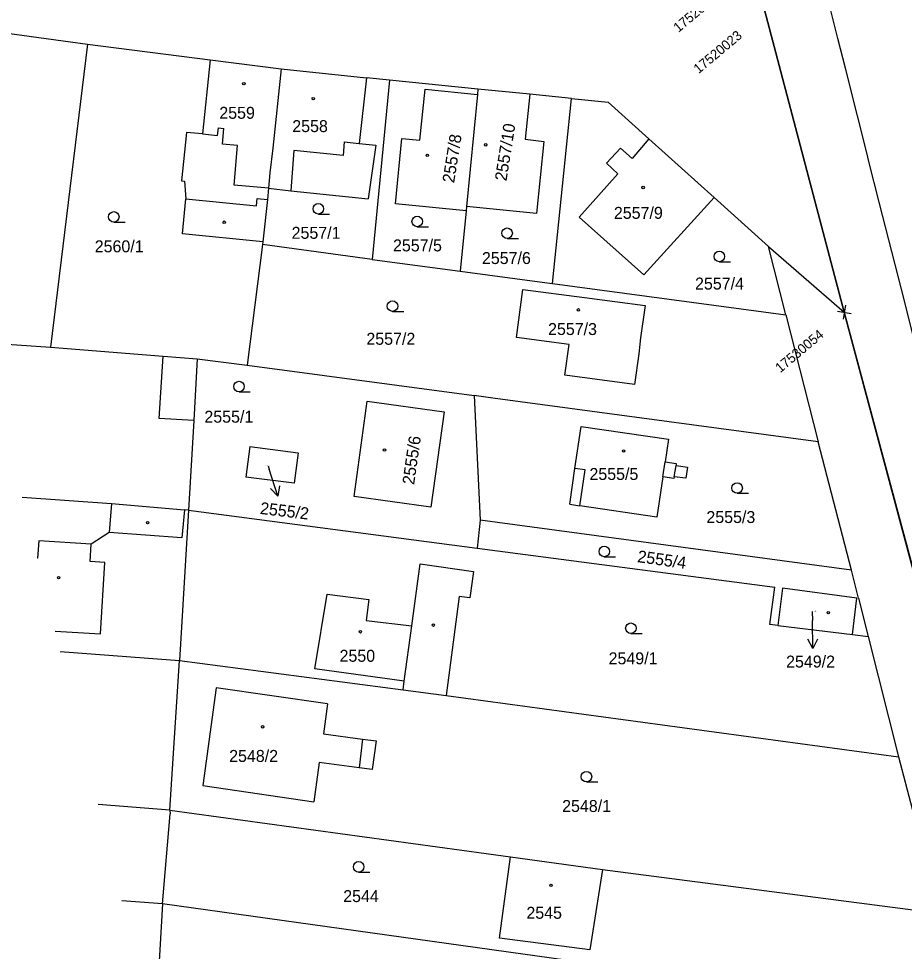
# Model space of a CAD drawing. Extents: x -754679 to -754173, y -1169241 to -1168288.
# Drawn here: x -754474.1 to -754379.7, y -1169048.7 to -1168949.2 of the extents above; entities that cross this region are included whole.
import ezdxf

# ---------------------------------------------------------------- set-up
doc = ezdxf.new("R2010")
doc.units = 0
for name, color, linetype in [('Vrstva 1', 7, 'Continuous'), ('Vrstva 16', 7, 'Continuous'), ('Vrstva 18', 7, 'Continuous'), ('Vrstva 19', 7, 'Continuous'), ('Vrstva 25', 7, 'Continuous'), ('Vrstva 4', 7, 'Continuous'), ('Vrstva 52', 7, 'Continuous'), ('Vrstva 53', 7, 'Continuous'), ('Vrstva 60', 7, 'Continuous')]:
    doc.layers.add(name, color=color, linetype=linetype)

msp = doc.modelspace()

# ---------------------------------------------------------------- linework, layer by layer
at = {"layer": 'Vrstva 1'}
for p, q in [((-754394.57, -1168948.26), (-754386.06, -1168980.52)), ((-754481.59, -1168949.91), (-754466.73, -1168951.94)), ((-754466.73, -1168951.94), (-754470.7, -1168984.24)), ((-754466.73, -1168951.94), (-754453.68, -1168953.61)), ((-754453.68, -1168953.61), (-754454.48, -1168961.5)), ((-754453.68, -1168953.61), (-754446.09, -1168954.58)), ((-754446.09, -1168954.58), (-754446.98, -1168963.03)), ((-754446.09, -1168954.58), (-754437, -1168955.53)), ((-754437, -1168955.53), (-754437.78, -1168962.52)), ((-754434.53, -1168955.78), (-754437, -1168955.53)), ((-754434.53, -1168955.78), (-754436.38, -1168974.88)), ((-754425.12, -1168956.72), (-754434.53, -1168955.78)), ((-754431.33, -1168962.16), (-754430.76, -1168956.72)), ((-754430.76, -1168956.72), (-754425.18, -1168957.29)), ((-754425.18, -1168957.29), (-754426.34, -1168969.24)), ((-754425.12, -1168956.72), (-754425.18, -1168957.29)), ((-754419.59, -1168957.27), (-754425.12, -1168956.72)), ((-754419.59, -1168957.27), (-754420.07, -1168962.07)), ((-754415.14, -1168957.72), (-754419.59, -1168957.27)), ((-754417.17, -1168977.46), (-754415.14, -1168957.72)), ((-754415.14, -1168957.72), (-754411.25, -1168958.11)), ((-754411.25, -1168958.11), (-754406.9, -1168962.02)), ((-754456.19, -1168961.34), (-754456.71, -1168966.5)), ((-754454.48, -1168961.5), (-754456.19, -1168961.34)), ((-754433.91, -1168968.96), (-754433.24, -1168962)), ((-754433.24, -1168962), (-754431.33, -1168962.16)), ((-754420.07, -1168962.07), (-754418.08, -1168962.31)), ((-754418.08, -1168962.31), (-754418.86, -1168969.98)), ((-754406.9, -1168962.02), (-754408.69, -1168964.11)), ((-754406.9, -1168962.02), (-754399.92, -1168968.29)), ((-754446.98, -1168963.03), (-754447.3, -1168965.65)), ((-754437.78, -1168962.52), (-754436.02, -1168962.72)), ((-754436.02, -1168962.72), (-754436.82, -1168968.44)), ((-754409.93, -1168963.02), (-754411.4, -1168964.64)), ((-754408.69, -1168964.11), (-754409.93, -1168963.02)), ((-754411.4, -1168964.64), (-754410.19, -1168965.77)), ((-754447.3, -1168965.65), (-754447.44, -1168967.3)), ((-754410.19, -1168965.77), (-754414.34, -1168970.38)), ((-754456.71, -1168966.5), (-754456.41, -1168966.53)), ((-754456.41, -1168966.53), (-754456.27, -1168968.44)), ((-754447.44, -1168967.3), (-754447.56, -1168968.51)), ((-754447.44, -1168967.3), (-754445.06, -1168967.58)), ((-754456.63, -1168972.16), (-754456.27, -1168968.44)), ((-754445.06, -1168967.58), (-754436.82, -1168968.44)), ((-754407.44, -1168976.53), (-754399.92, -1168968.29)), ((-754399.92, -1168968.29), (-754394.13, -1168973.5)), ((-754447.56, -1168968.51), (-754448.05, -1168973.02)), ((-754426.39, -1168969.71), (-754433.91, -1168968.96)), ((-754426.34, -1168969.24), (-754426.39, -1168969.71)), ((-754418.86, -1168969.98), (-754426.34, -1168969.24)), ((-754426.39, -1168969.71), (-754427.02, -1168976.13)), ((-754414.34, -1168970.38), (-754407.44, -1168976.53)), ((-754448.05, -1168973.02), (-754456.63, -1168972.16)), ((-754448.09, -1168973.3), (-754449.71, -1168986.17)), ((-754448.05, -1168973.02), (-754448.09, -1168973.3)), ((-754436.38, -1168974.88), (-754448.09, -1168973.3)), ((-754394.13, -1168973.5), (-754386.06, -1168980.52)), ((-754392.28, -1168980.8), (-754394.13, -1168973.5)), ((-754436.38, -1168974.88), (-754427.02, -1168976.13)), ((-754427.02, -1168976.13), (-754418.28, -1168977.31)), ((-754418.28, -1168977.31), (-754417.17, -1168977.46)), ((-754421.01, -1168983.23), (-754420.33, -1168978.08)), ((-754420.33, -1168978.08), (-754413.76, -1168978.94)), ((-754417.17, -1168977.46), (-754392.28, -1168980.8)), ((-754413.76, -1168978.94), (-754407.29, -1168979.79)), ((-754407.29, -1168979.79), (-754407.79, -1168983.26)), ((-754392.28, -1168980.8), (-754388.85, -1168994.33)), ((-754386.06, -1168980.52), (-754345.91, -1169130.8)), ((-754415.4, -1168983.97), (-754421.01, -1168983.23)), ((-754407.79, -1168983.26), (-754407.98, -1168984.94)), ((-754477.805, -1168983.743), (-754470.7, -1168984.24)), ((-754470.7, -1168984.24), (-754458.69, -1168985.2)), ((-754415.84, -1168987.24), (-754415.4, -1168983.97)), ((-754458.69, -1168985.2), (-754455.05, -1168985.5)), ((-754407.98, -1168984.94), (-754408.42, -1168988.22)), ((-754455.05, -1168985.5), (-754455.42, -1168992.07)), ((-754455.05, -1168985.5), (-754449.71, -1168986.17)), ((-754449.71, -1168986.17), (-754425.52, -1168989.41)), ((-754408.42, -1168988.22), (-754415.84, -1168987.24)), ((-754438.33, -1169000.18), (-754436.92, -1168989.99)), ((-754436.92, -1168989.99), (-754428.72, -1168991.13)), ((-754425.52, -1168989.41), (-754424.88, -1169002.68)), ((-754423.54, -1168989.68), (-754425.52, -1168989.41)), ((-754388.85, -1168994.33), (-754423.54, -1168989.68)), ((-754428.72, -1168991.13), (-754430.14, -1169001.31)), ((-754455.42, -1168992.07), (-754455.96, -1169001.63)), ((-754414.78, -1168997.18), (-754414.13, -1168992.71)), ((-754414.13, -1168992.71), (-754404.82, -1168994.06)), ((-754404.82, -1168994.06), (-754405.17, -1168996.48)), ((-754385.31, -1169008.03), (-754388.85, -1168994.33)), ((-754449.45, -1168994.84), (-754449.88, -1168998.11)), ((-754449.45, -1168994.84), (-754444.3, -1168995.53)), ((-754444.3, -1168995.53), (-754444.71, -1168998.76)), ((-754415.33, -1169000.99), (-754414.78, -1168997.18)), ((-754405.17, -1168996.48), (-754403.97, -1168996.66)), ((-754403.97, -1168996.66), (-754404, -1168996.86)), ((-754404, -1168996.86), (-754402.76, -1168997.04)), ((-754402.76, -1168997.04), (-754402.95, -1168998.23)), ((-754444.71, -1168998.76), (-754449.88, -1168998.11)), ((-754405.4, -1168998.07), (-754406.03, -1169002.37)), ((-754404.22, -1168998.25), (-754405.4, -1168998.07)), ((-754404.19, -1168998.06), (-754404.22, -1168998.25)), ((-754402.95, -1168998.23), (-754404.19, -1168998.06)), ((-754473.723, -1169000.249), (-754464.18, -1169000.91)), ((-754430.14, -1169001.31), (-754438.33, -1169000.18)), ((-754464.18, -1169000.91), (-754464.45, -1169004)), ((-754464.18, -1169000.91), (-754456.41, -1169001.59)), ((-754415.33, -1169000.99), (-754414.24, -1169001.17)), ((-754406.03, -1169002.37), (-754414.24, -1169001.17)), ((-754455.96, -1169001.63), (-754456.93, -1169017.66)), ((-754455.96, -1169001.63), (-754456.41, -1169001.59)), ((-754455.96, -1169001.63), (-754425.19, -1169005.68)), ((-754424.88, -1169002.68), (-754425.19, -1169005.68)), ((-754385.31, -1169008.03), (-754424.88, -1169002.68)), ((-754464.45, -1169004), (-754466.34, -1169005.26)), ((-754471.95, -1169004.9), (-754472.07, -1169006.74)), ((-754466.34, -1169005.26), (-754471.95, -1169004.9)), ((-754425.19, -1169005.68), (-754393.45, -1169009.86)), ((-754472.07, -1169006.74), (-754472.119, -1169006.737)), ((-754432.17, -1169013.97), (-754431.27, -1169007.35)), ((-754431.27, -1169007.35), (-754425.59, -1169008.18)), ((-754425.59, -1169008.18), (-754425.97, -1169010.98)), ((-754384.54, -1169011.03), (-754385.31, -1169008.03)), ((-754394.01, -1169013.82), (-754393.45, -1169009.86)), ((-754392.65, -1169009.96), (-754393.13, -1169013.93)), ((-754384.71, -1169011.01), (-754392.65, -1169009.96)), ((-754442.51, -1169018.57), (-754441.18, -1169010.6)), ((-754441.18, -1169010.6), (-754436.76, -1169011.15)), ((-754436.76, -1169011.15), (-754437.04, -1169013.4)), ((-754427.11, -1169010.83), (-754428.52, -1169021.39)), ((-754425.97, -1169010.98), (-754427.11, -1169010.83)), ((-754385.17, -1169014.89), (-754384.71, -1169011.01)), ((-754384.54, -1169011.03), (-754383.51, -1169015.1)), ((-754437.04, -1169013.4), (-754432.17, -1169013.97)), ((-754393.13, -1169013.93), (-754394.01, -1169013.82)), ((-754393.13, -1169013.93), (-754385.17, -1169014.89)), ((-754385.17, -1169014.89), (-754383.51, -1169015.1)), ((-754383.51, -1169015.1), (-754380.27, -1169027.93)), ((-754469.656, -1169016.696), (-754456.93, -1169017.66)), ((-754457.95, -1169033.61), (-754456.93, -1169017.66)), ((-754456.93, -1169017.66), (-754433.1, -1169020.78)), ((-754432.97, -1169019.86), (-754442.51, -1169018.57)), ((-754433.1, -1169020.78), (-754432.97, -1169019.86)), ((-754453.03, -1169020.58), (-754454.46, -1169030.99)), ((-754441.16, -1169022.27), (-754453.03, -1169020.58)), ((-754433.1, -1169020.78), (-754428.52, -1169021.39)), ((-754428.52, -1169021.39), (-754380.27, -1169027.93)), ((-754441.16, -1169022.27), (-754441.59, -1169025.49)), ((-754441.59, -1169025.49), (-754437.41, -1169026.05)), ((-754437.41, -1169026.05), (-754435.98, -1169026.24)), ((-754435.98, -1169026.24), (-754436.39, -1169029.3)), ((-754380.27, -1169027.93), (-754375.93, -1169044.62)), ((-754442.04, -1169028.55), (-754442.6, -1169032.74)), ((-754437.79, -1169029.11), (-754442.04, -1169028.55)), ((-754436.39, -1169029.3), (-754437.79, -1169029.11)), ((-754454.46, -1169030.99), (-754442.6, -1169032.74)), ((-754457.95, -1169033.61), (-754465.619, -1169033.022)), ((-754458.74, -1169043.6), (-754457.93, -1169034.01)), ((-754457.95, -1169033.61), (-754421.64, -1169038.61)), ((-754457.95, -1169033.61), (-754457.93, -1169034.01)), ((-754422.81, -1169047.28), (-754421.64, -1169038.61)), ((-754421.64, -1169038.61), (-754411.85, -1169039.94)), ((-754411.85, -1169039.94), (-754413.18, -1169048.53)), ((-754411.85, -1169039.94), (-754375.93, -1169044.62)), ((-754458.74, -1169043.6), (-754463.076, -1169043.306)), ((-754458.74, -1169043.6), (-754459.562, -1169057.515)), ((-754373.03, -1169055.57), (-754458.74, -1169043.6)), ((-754413.18, -1169048.53), (-754422.81, -1169047.28))]:
    msp.add_line(p, q, dxfattribs=at)
for points in [[(-754384.656, -1168959.571), (-754385.936, -1168954.491), (-754386.734, -1168951.322), (-754387.865, -1168946.893), (-754387.928, -1168946.598), (-754389.016, -1168942.293), (-754391.2, -1168933.67), (-754393.647, -1168923.979), (-754396.084, -1168914.315), (-754398.294, -1168905.574)], [(-754382.327, -1168968.778), (-754383.436, -1168964.432), (-754383.656, -1168963.522), (-754384.656, -1168959.571)], [(-754371.756, -1169010.617), (-754373.805, -1169002.503), (-754376.012, -1168993.767), (-754377.617, -1168987.413), (-754379.98, -1168978.062), (-754382.327, -1168968.778)]]:
    msp.add_lwpolyline(points, dxfattribs=at)
at = {"layer": 'Vrstva 16'}
for p, q in [((-754447.5, -1168996.9), (-754447.38, -1168997.27)), ((-754446.455, -1169000.124), (-754447.38, -1168997.27)), ((-754389.47, -1169012.45), (-754389.46, -1169013.39)), ((-754389.42, -1169016.39), (-754389.46, -1169013.39))]:
    msp.add_line(p, q, dxfattribs=at)
for points in [[(-754446.288, -1168999.018), (-754446.455, -1169000.124), (-754447.239, -1168999.327)], [(-754388.933, -1169015.383), (-754389.42, -1169016.39), (-754389.933, -1169015.397)]]:
    msp.add_lwpolyline(points, dxfattribs=at)
at = {"layer": 'Vrstva 25'}
for p, q in [((-754442.13, -1168970.05), (-754440.93, -1168970.05)), ((-754463.94, -1168970.92), (-754462.74, -1168970.92)), ((-754431.59, -1168971.4), (-754430.39, -1168971.4)), ((-754422.01, -1168972.66), (-754420.81, -1168972.66)), ((-754399.38, -1168975.13), (-754398.18, -1168975.13)), ((-754434.23, -1168980.43), (-754433.03, -1168980.43)), ((-754450.59, -1168989.01), (-754449.39, -1168989.01)), ((-754397.49, -1168999.83), (-754396.29, -1168999.83)), ((-754411.65, -1169006.59), (-754410.45, -1169006.59)), ((-754408.81, -1169014.78), (-754407.61, -1169014.78)), ((-754413.55, -1169030.62), (-754412.35, -1169030.62)), ((-754437.84, -1169040.23), (-754436.64, -1169040.23))]:
    msp.add_line(p, q, dxfattribs=at)
for centre, radius in [((-754450.08, -1168956.15), 0.131), ((-754442.68, -1168957.75), 0.131), ((-754424.29, -1168962.67), 0.131), ((-754430.52, -1168963.79), 0.131), ((-754407.51, -1168967.22), 0.131), ((-754442.13, -1168969.488), 0.562), ((-754463.94, -1168970.357), 0.562), ((-754431.59, -1168970.838), 0.562), ((-754452.17, -1168970.92), 0.131), ((-754422.01, -1168972.097), 0.562), ((-754399.38, -1168974.568), 0.562), ((-754434.23, -1168979.867), 0.562), ((-754414.41, -1168980.27), 0.131), ((-754450.59, -1168988.448), 0.562), ((-754435.08, -1168995.22), 0.131), ((-754409.59, -1168995.31), 0.131), ((-754397.49, -1168999.268), 0.562), ((-754460.33, -1169002.96), 0.131), ((-754411.65, -1169006.028), 0.562), ((-754469.82, -1169008.83), 0.131), ((-754387.77, -1169012.56), 0.131), ((-754429.87, -1169013.89), 0.131), ((-754408.81, -1169014.218), 0.562), ((-754437.65, -1169014.6), 0.131), ((-754448.08, -1169024.74), 0.131), ((-754413.55, -1169030.058), 0.562), ((-754437.84, -1169039.667), 0.562), ((-754417.34, -1169041.65), 0.131)]:
    msp.add_circle(centre, radius, dxfattribs=at)
at = {"layer": 'Vrstva 4'}
for p, q in [((-754454.48, -1168961.5), (-754452.87, -1168961.66)), ((-754452.87, -1168961.66), (-754452.79, -1168960.85)), ((-754452.79, -1168960.85), (-754452.21, -1168960.92)), ((-754452.35, -1168962.61), (-754452.21, -1168960.92)), ((-754439.39, -1168962.34), (-754439.48, -1168963.81)), ((-754439.39, -1168962.34), (-754437.78, -1168962.52)), ((-754450.76, -1168962.75), (-754452.35, -1168962.61)), ((-754451.12, -1168966.98), (-754450.76, -1168962.75)), ((-754444.75, -1168963.26), (-754445.06, -1168967.58)), ((-754439.48, -1168963.81), (-754444.75, -1168963.26)), ((-754447.44, -1168967.3), (-754451.12, -1168966.98)), ((-754456.27, -1168968.44), (-754448.74, -1168969.19)), ((-754448.74, -1168969.19), (-754448.66, -1168968.4)), ((-754448.66, -1168968.4), (-754447.56, -1168968.51)), ((-754459.11, -1168991.86), (-754458.69, -1168985.2)), ((-754455.42, -1168992.07), (-754459.11, -1168991.86)), ((-754413.68, -1168997.34), (-754414.78, -1168997.18)), ((-754405.4, -1168998.07), (-754405.17, -1168996.48)), ((-754404.19, -1168998.06), (-754404, -1168996.86)), ((-754414.24, -1169001.17), (-754413.68, -1168997.34)), ((-754456.41, -1169001.59), (-754456.67, -1169004.58)), ((-754456.67, -1169004.58), (-754464.45, -1169004)), ((-754466.46, -1169007.1), (-754466.34, -1169005.26)), ((-754464.9, -1169007.2), (-754466.46, -1169007.1)), ((-754465.36, -1169014.82), (-754464.9, -1169007.2)), ((-754432.97, -1169019.86), (-754432.17, -1169013.97)), ((-754470.193, -1169014.523), (-754465.36, -1169014.82)), ((-754437.41, -1169026.05), (-754437.79, -1169029.11))]:
    msp.add_line(p, q, dxfattribs=at)
at = {"layer": 'Vrstva 53'}
msp.add_lwpolyline([(-754345.91, -1169130.8), (-754386.06, -1168980.52), (-754394.57, -1168948.26)], dxfattribs=at)
at = {"layer": 'Vrstva 60'}
for p, q in [((-754386.799, -1168980.39), (-754385.321, -1168980.65)), ((-754385.93, -1168979.781), (-754386.19, -1168981.259))]:
    msp.add_line(p, q, dxfattribs=at)

# ---------------------------------------------------------------- texts
at = {"layer": 'Vrstva 16'}
for s, rotation, p in [('2555/2', 353.17119, (-754448.398, -1169002.023)), ('2549/2', 360, (-754392.267, -1169018.415))]:
    msp.add_text(s, height=1.275, rotation=rotation, dxfattribs=at).set_placement(p)
at = {"layer": 'Vrstva 18'}
for s, rotation, p in [('2557/1', 360, (-754444.983, -1168972.69)), ('2560/1', 360, (-754465.973, -1168974.13)), ('2557/5', 360, (-754434.173, -1168974.03)), ('2557/6', 360, (-754424.693, -1168975.38)), ('2557/4', 360, (-754401.973, -1168978.1)), ('2557/2', 360, (-754437.013, -1168983.99)), ('2555/1', 360, (-754454.283, -1168992.3)), ('2555/3', 360, (-754400.763, -1169003)), ('2555/4', 351.91068, (-754408.175, -1169007.163)), ('2549/1', 360, (-754411.188, -1169018.07)), ('2548/1', 360, (-754416.143, -1169033.82)), ('2544', 360, (-754439.483, -1169043.43))]:
    msp.add_text(s, height=1.275, rotation=rotation, dxfattribs=at).set_placement(p)
msp.add_text('2555/2', height=0.1, dxfattribs=at).set_placement((-754447.759, -1168996.9))
at = {"layer": 'Vrstva 19'}
for s, rotation, p in [('2559', 360, (-754452.693, -1168959.89)), ('2558', 360, (-754444.913, -1168961.31)), ('2557/10', 81.01623, (-754422.077, -1168966.588)), ('2557/8', 81.01623, (-754427.661, -1168966.791)), ('2557/9', 360, (-754410.623, -1168970.56)), ('2557/3', 360, (-754417.643, -1168982.95)), ('2555/6', 81.87567, (-754431.926, -1168998.971)), ('2555/5', 360, (-754413.233, -1168998.41)), ('2550', 360, (-754439.873, -1169017.8)), ('2548/2', 360, (-754451.643, -1169028.48)), ('2545', 360, (-754419.953, -1169045.21))]:
    msp.add_text(s, height=1.275, rotation=rotation, dxfattribs=at).set_placement(p)
msp.add_text('2549/2', height=0.1, dxfattribs=at).set_placement((-754389.456, -1169012.45))
at = {"layer": 'Vrstva 52'}
for s, p in [(' 17520021', (-754404.042, -1168950.984)), (' 17520023', (-754401.891, -1168955.383)), (' 17530054', (-754393.181, -1168987.277))]:
    msp.add_text(s, height=1.0368, rotation=40, dxfattribs=at).set_placement(p)

doc.saveas('drawing.dxf')
